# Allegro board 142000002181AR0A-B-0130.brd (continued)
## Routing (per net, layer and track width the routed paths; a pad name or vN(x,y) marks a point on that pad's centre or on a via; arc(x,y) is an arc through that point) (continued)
GND_1: length 19.4
  BOTTOM w0.381: H1.4 9.2,50.8 C6.1 7.87,49.78 5.29,52.37 H1.5 ; H1.3 11.37,55 C1.1 10.25,56.86 H1.2
GND_2: length 22.3
  BOTTOM w0.381: H5.4 9.68,26.14 C12.1 10.07,29.86 H5.2 6.86,32.82 C9.1 3.14,32.66 H5.8
GND_3: length 21.3
  BOTTOM w0.381: H2.4 124.57,53.14 C3.1 124.8,56.86 H2.2 ; H2.8 115.48,56.86 C2.1 115.72,53.14 H2.6
GND_4: length 21.8
  BOTTOM w0.381: H7.4 327.44,26.14 C13.1 327.83,29.86 H7.2 324.86,32.83 C11.1 321.14,32.65 H7.8
GND_5: length 21.8
  BOTTOM w0.381: H6.2 121.86,32.63 C10.1 118.14,32.85 H6.8 ; H6.6 118.14,23.28 C15.1 121.86,23.51 H6.4
GND_6: length 19.4
  BOTTOM w0.381: H3.5 258.13,50.24 C7.1 260.35,50.65 H3.4 260.2,53.14 C4.1 260.44,56.86 H3.2
GND_7: length 27.2
  BOTTOM w0.381: H9.7 252.58,5.79 C18.1 247.2,6.86 H9.8 ; H9.2 258.29,6.86 260.35,8.92 C17.1 259.28,9.91 258.83,9.91 256.55,7.63 H9.1
GND_8: length 21.5
  BOTTOM w0.381: H8.7 381.88,20 C16.1 382.07,20.63 383.3,21.86 H8.8 383.54,24.46 C14.1 384.16,26.47 H8.1
GND_9: length 19.3
  BOTTOM w0.381: H4.6 383.69,53.14 C5.1 383.45,56.86 H4.8 ; H4.5 388,49.08 C8.1 388.37,48.77 389.86,50.26 H4.4
MB_PDU_SCL_R: length 10.7
  BOTTOM w0.127: R29.2 270.96,13.01 v1(270.51,13.46) 269.59,12.54 269.59,7.12 270.11,6.61 270.99,6.61 CONN6.4
MB_PDU_SDA_R: length 6.9
  BOTTOM w0.127: R30.1 273.61,13.01 v1(274.07,13.46) 274.07,11.61 272.92,10.46 CONN6.5
PDU_12V: length 1887.2
  V3 w0.635: CONN2.P1-11 95.58,20.46 ; CONN2.P1-11 94.64,19.52 ; CONN2.P1-11 93.69,20.46 ; CONN2.P1-11 94.64,21.4 ; CONN3.P1-23 145.18,20.46 ; CONN3.P1-23 143.29,20.46 ; CONN3.P1-23 144.23,19.52 ; CONN3.P1-23 144.23,21.4 ; CONN2.P3-13 90.5,17.92 ; CONN2.P3-13 89.56,18.86 ; CONN2.P3-13 88.61,17.92 ; CONN2.P3-13 89.56,16.98 ; CONN5.P1 330.14,12.65 ; CONN5.P1 328.95,11.46 ; CONN5.P1 328.95,13.84 ; CONN4.P3-21 211.62,18.86 ; CONN4.P3-21 212.56,17.92 ; CONN4.P3-21 210.67,17.92 ; CONN4.P3-21 211.62,16.98 ; 84.48,16.98 CONN2.P3-22 ; CONN2.P3-22 85.42,17.92 ; CONN2.P3-22 83.53,17.92 ; CONN2.P3-22 84.48,18.86 ; CONN3.P1-22 147.72,20.46 ; CONN3.P1-22 146.77,19.52 ; CONN3.P1-22 146.77,21.4 ; CONN3.P1-22 145.83,20.46 ; CONN1.P3-21 25.66,17.92 ; CONN1.P3-21 24.71,16.98 ; CONN1.P3-21 23.77,17.92 ; CONN1.P3-21 24.71,18.86 ; CONN4.P3-22 210.02,17.92 ; CONN4.P3-22 209.08,16.98 ; CONN4.P3-22 209.08,18.86 ; CONN4.P3-22 208.13,17.92 ; CONN4.P1-21 212.56,20.46 ; CONN4.P1-21 211.62,21.4 ; CONN4.P1-21 211.62,19.52 ; CONN4.P1-21 210.67,20.46 ; CONN1.P1-13 28.2,20.46 ; CONN1.P1-13 27.25,21.4 ; CONN1.P1-13 26.31,20.46 ; CONN1.P1-13 27.25,19.52 ; CONN1.P3-13 28.2,17.92 ; CONN1.P3-13 27.25,16.98 ; CONN1.P3-13 26.31,17.92 ; CONN1.P3-13 27.25,18.86 ; 326.65,11.46 CONN5.P2 ; CONN5.P2 325.46,12.65 ; CONN5.P2 326.65,13.84 ; 18.69,20.46 CONN1.P1-23 ; CONN1.P1-23 19.63,21.4 ; CONN1.P1-23 20.58,20.46 ; CONN1.P1-23 19.63,19.52 ; 86.07,20.46 CONN2.P1-21 ; CONN2.P1-21 87.02,21.4 ; CONN2.P1-21 87.96,20.46 ; CONN2.P1-21 87.02,19.52 ; 28.85,17.92 CONN1.P3-12 ; CONN1.P3-12 30.74,17.92 ; CONN1.P3-12 29.79,18.86 ; CONN1.P3-12 29.79,16.98 ; CONN3.P1-13 152.8,20.46 ; CONN3.P1-13 151.85,21.4 ; CONN3.P1-13 151.85,19.52 ; CONN3.P1-13 150.91,20.46 ; CONN1.P3-22 22.17,18.86 ; CONN1.P3-22 21.23,17.92 ; CONN1.P3-22 23.12,17.92 ; CONN1.P3-22 22.17,16.98 ; 19.63,16.98 CONN1.P3-23 ; CONN1.P3-23 20.58,17.92 ; CONN1.P3-23 19.63,18.86 ; CONN1.P3-23 18.69,17.92 ; 215.75,20.46 CONN4.P1-12 ; CONN4.P1-12 216.7,19.52 ; CONN4.P1-12 216.7,21.4 ; CONN4.P1-12 217.64,20.46 ; CONN2.P1-23 82.88,20.46 ; CONN2.P1-23 81.94,19.52 ; CONN2.P1-23 80.99,20.46 ; CONN2.P1-23 81.94,21.4 ; 206.54,16.98 CONN4.P3-23 ; CONN4.P3-23 206.54,18.86 ; CONN4.P3-23 205.59,17.92 ; CONN4.P3-23 207.48,17.92 ; 213.21,20.46 CONN4.P1-13 ; CONN4.P1-13 215.1,20.46 ; CONN4.P1-13 214.16,19.52 ; CONN4.P1-13 214.16,21.4 ; 148.37,20.46 CONN3.P1-21 ; CONN3.P1-21 149.31,19.52 ; CONN3.P1-21 149.31,21.4 ; CONN3.P1-21 150.26,20.46 ; 146.77,16.98 CONN3.P3-22 ; CONN3.P3-22 146.77,18.86 ; CONN3.P3-22 145.83,17.92 ; CONN3.P3-22 147.72,17.92 ; 155.99,20.46 CONN3.P1-11 ; CONN3.P1-11 156.93,19.52 ; CONN3.P1-11 157.88,20.46 ; CONN3.P1-11 156.93,21.4 ; 205.59,20.46 CONN4.P1-23 ; CONN4.P1-23 206.54,19.52 ; CONN4.P1-23 206.54,21.4 ; CONN4.P1-23 207.48,20.46 ; CONN2.P3-23 81.94,18.86 ; CONN2.P3-23 82.88,17.92 ; CONN2.P3-23 81.94,16.98 ; CONN2.P3-23 80.99,17.92 ; CONN2.P3-21 87.02,18.86 ; CONN2.P3-21 87.02,16.98 ; CONN2.P3-21 87.96,17.92 ; CONN2.P3-21 86.07,17.92 ; CONN4.P1-11 219.24,21.4 ; CONN4.P1-11 218.29,20.46 ; CONN4.P1-11 220.18,20.46 ; CONN4.P1-11 219.24,19.52 ; 219.24,16.98 CONN4.P3-11 ; CONN4.P3-11 220.18,17.92 ; CONN4.P3-11 219.24,18.86 ; CONN4.P3-11 218.29,17.92 ; CONN2.P1-22 85.42,20.46 ; CONN2.P1-22 84.48,21.4 ; CONN2.P1-22 83.53,20.46 ; CONN2.P1-22 84.48,19.52 ; CONN3.P1-12 154.39,21.4 ; CONN3.P1-12 154.39,19.52 ; CONN3.P1-12 153.45,20.46 ; CONN3.P1-12 155.34,20.46 ; 32.33,19.52 CONN1.P1-11 ; CONN1.P1-11 33.28,20.46 ; CONN1.P1-11 32.33,21.4 ; CONN1.P1-11 31.39,20.46 ; 94.64,16.98 CONN2.P3-11 ; CONN2.P3-11 94.64,18.86 ; CONN2.P3-11 93.69,17.92 ; CONN2.P3-11 95.58,17.92 ; 24.71,19.52 CONN1.P1-21 ; CONN1.P1-21 23.77,20.46 ; CONN1.P1-21 24.71,21.4 ; CONN1.P1-21 25.66,20.46 ; CONN3.P3-11 157.88,17.92 ; CONN3.P3-11 156.93,18.86 ; CONN3.P3-11 156.93,16.98 ; CONN3.P3-11 155.99,17.92 ; 151.85,16.98 CONN3.P3-13 ; CONN3.P3-13 150.91,17.92 ; CONN3.P3-13 151.85,18.86 ; CONN3.P3-13 152.8,17.92 ; 148.37,17.92 CONN3.P3-21 ; CONN3.P3-21 150.26,17.92 ; CONN3.P3-21 149.31,16.98 ; CONN3.P3-21 149.31,18.86 ; 153.45,17.92 CONN3.P3-12 ; CONN3.P3-12 155.34,17.92 ; CONN3.P3-12 154.39,16.98 ; CONN3.P3-12 154.39,18.86 ; 31.39,17.92 CONN1.P3-11 ; CONN1.P3-11 33.28,17.92 ; CONN1.P3-11 32.33,16.98 ; CONN1.P3-11 32.33,18.86 ; CONN1.P1-12 29.79,21.4 ; CONN1.P1-12 30.74,20.46 ; CONN1.P1-12 28.85,20.46 ; CONN1.P1-12 29.79,19.52 ; CONN4.P3-13 214.16,18.86 ; CONN4.P3-13 213.21,17.92 ; CONN4.P3-13 214.16,16.98 ; CONN4.P3-13 215.1,17.92 ; 21.23,20.46 CONN1.P1-22 ; CONN1.P1-22 22.17,21.4 ; CONN1.P1-22 23.12,20.46 ; CONN1.P1-22 22.17,19.52 ; 215.75,17.92 CONN4.P3-12 ; CONN4.P3-12 216.7,16.98 ; CONN4.P3-12 217.64,17.92 ; CONN4.P3-12 216.7,18.86 ; CONN2.P1-12 92.1,21.4 ; CONN2.P1-12 91.15,20.46 ; CONN2.P1-12 93.04,20.46 ; CONN2.P1-12 92.1,19.52 ; 143.29,17.92 CONN3.P3-23 ; CONN3.P3-23 145.18,17.92 ; CONN3.P3-23 144.23,16.98 ; CONN3.P3-23 144.23,18.86 ; 91.15,17.92 CONN2.P3-12 ; CONN2.P3-12 92.1,18.86 ; CONN2.P3-12 92.1,16.98 ; CONN2.P3-12 93.04,17.92 ; CONN2.P1-13 89.56,21.4 ; CONN2.P1-13 88.61,20.46 ; CONN2.P1-13 89.56,19.52 ; CONN2.P1-13 90.5,20.46 ; CONN4.P1-22 209.08,21.4 ; CONN4.P1-22 210.02,20.46 ; CONN4.P1-22 208.13,20.46 ; CONN4.P1-22 209.08,19.52
  V5 w0.635: 92.1,16.98 CONN2.P3-12 ; CONN2.P3-12 93.04,17.92 ; CONN2.P3-12 92.1,18.86 ; CONN2.P3-12 91.15,17.92 ; CONN1.P3-11 32.33,18.86 ; CONN1.P3-11 33.28,17.92 ; CONN1.P3-11 31.39,17.92 ; CONN1.P3-11 32.33,16.98 ; 81.94,16.98 CONN2.P3-23 ; CONN2.P3-23 82.88,17.92 ; CONN2.P3-23 80.99,17.92 ; CONN2.P3-23 81.94,18.86 ; CONN3.P3-12 154.39,18.86 ; CONN3.P3-12 153.45,17.92 ; CONN3.P3-12 154.39,16.98 ; CONN3.P3-12 155.34,17.92 ; CONN3.P3-23 145.18,17.92 ; CONN3.P3-23 143.29,17.92 ; CONN3.P3-23 144.23,16.98 ; CONN3.P3-23 144.23,18.86 ; CONN3.P3-22 146.77,18.86 ; CONN3.P3-22 147.72,17.92 ; CONN3.P3-22 146.77,16.98 ; CONN3.P3-22 145.83,17.92 ; CONN2.P1-11 94.64,21.4 ; CONN2.P1-11 93.69,20.46 ; CONN2.P1-11 94.64,19.52 ; CONN2.P1-11 95.58,20.46 ; 156.93,19.52 CONN3.P1-11 ; CONN3.P1-11 155.99,20.46 ; CONN3.P1-11 157.88,20.46 ; CONN3.P1-11 156.93,21.4 ; 153.45,20.46 CONN3.P1-12 ; CONN3.P1-12 154.39,19.52 ; CONN3.P1-12 154.39,21.4 ; CONN3.P1-12 155.34,20.46 ; 22.17,16.98 CONN1.P3-22 ; CONN1.P3-22 22.17,18.86 ; CONN1.P3-22 23.12,17.92 ; CONN1.P3-22 21.23,17.92 ; CONN2.P3-13 90.5,17.92 ; CONN2.P3-13 88.61,17.92 ; CONN2.P3-13 89.56,18.86 ; CONN2.P3-13 89.56,16.98 ; CONN3.P1-23 145.18,20.46 ; CONN3.P1-23 143.29,20.46 ; CONN3.P1-23 144.23,21.4 ; CONN3.P1-23 144.23,19.52 ; 24.71,16.98 CONN1.P3-21 ; CONN1.P3-21 23.77,17.92 ; CONN1.P3-21 24.71,18.86 ; CONN1.P3-21 25.66,17.92 ; 27.25,16.98 CONN1.P3-13 ; CONN1.P3-13 28.2,17.92 ; CONN1.P3-13 27.25,18.86 ; CONN1.P3-13 26.31,17.92 ; CONN4.P1-11 219.24,21.4 ; CONN4.P1-11 219.24,19.52 ; CONN4.P1-11 218.29,20.46 ; CONN4.P1-11 220.18,20.46 ; CONN3.P3-21 149.31,18.86 ; CONN3.P3-21 150.26,17.92 ; CONN3.P3-21 148.37,17.92 ; CONN3.P3-21 149.31,16.98 ; CONN3.P3-13 152.8,17.92 ; CONN3.P3-13 151.85,16.98 ; CONN3.P3-13 150.91,17.92 ; CONN3.P3-13 151.85,18.86 ; CONN1.P1-22 22.17,21.4 ; CONN1.P1-22 21.23,20.46 ; CONN1.P1-22 23.12,20.46 ; CONN1.P1-22 22.17,19.52 ; CONN3.P1-13 152.8,20.46 ; CONN3.P1-13 151.85,19.52 ; CONN3.P1-13 151.85,21.4 ; CONN3.P1-13 150.91,20.46 ; CONN2.P1-12 93.04,20.46 ; CONN2.P1-12 92.1,19.52 ; CONN2.P1-12 92.1,21.4 ; CONN2.P1-12 91.15,20.46 ; 211.62,19.52 CONN4.P1-21 ; CONN4.P1-21 210.67,20.46 ; CONN4.P1-21 211.62,21.4 ; CONN4.P1-21 212.56,20.46 ; 84.48,19.52 CONN2.P1-22 ; CONN2.P1-22 85.42,20.46 ; CONN2.P1-22 83.53,20.46 ; CONN2.P1-22 84.48,21.4 ; 328.95,11.46 CONN5.P1 ; CONN5.P1 328.95,13.84 ; CONN5.P1 330.14,12.65 ; CONN4.P3-23 206.54,18.86 ; CONN4.P3-23 206.54,16.98 ; CONN4.P3-23 205.59,17.92 ; CONN4.P3-23 207.48,17.92 ; 29.79,16.98 CONN1.P3-12 ; CONN1.P3-12 30.74,17.92 ; CONN1.P3-12 29.79,18.86 ; CONN1.P3-12 28.85,17.92 ; CONN1.P1-21 24.71,21.4 ; CONN1.P1-21 24.71,19.52 ; CONN1.P1-21 25.66,20.46 ; CONN1.P1-21 23.77,20.46 ; 28.85,20.46 CONN1.P1-12 ; CONN1.P1-12 29.79,19.52 ; CONN1.P1-12 29.79,21.4 ; CONN1.P1-12 30.74,20.46 ; 86.07,20.46 CONN2.P1-21 ; CONN2.P1-21 87.02,21.4 ; CONN2.P1-21 87.96,20.46 ; CONN2.P1-21 87.02,19.52 ; CONN4.P3-12 217.64,17.92 ; CONN4.P3-12 216.7,16.98 ; CONN4.P3-12 215.75,17.92 ; CONN4.P3-12 216.7,18.86 ; 26.31,20.46 CONN1.P1-13 ; CONN1.P1-13 28.2,20.46 ; CONN1.P1-13 27.25,19.52 ; CONN1.P1-13 27.25,21.4 ; 205.59,20.46 CONN4.P1-23 ; CONN4.P1-23 206.54,21.4 ; CONN4.P1-23 206.54,19.52 ; CONN4.P1-23 207.48,20.46 ; CONN4.P3-11 220.18,17.92 ; CONN4.P3-11 218.29,17.92 ; CONN4.P3-11 219.24,16.98 ; CONN4.P3-11 219.24,18.86 ; 89.56,19.52 CONN2.P1-13 ; CONN2.P1-13 90.5,20.46 ; CONN2.P1-13 89.56,21.4 ; CONN2.P1-13 88.61,20.46 ; 83.53,17.92 CONN2.P3-22 ; CONN2.P3-22 84.48,16.98 ; CONN2.P3-22 84.48,18.86 ; CONN2.P3-22 85.42,17.92 ; 86.07,17.92 CONN2.P3-21 ; CONN2.P3-21 87.02,16.98 ; CONN2.P3-21 87.02,18.86 ; CONN2.P3-21 87.96,17.92 ; 18.69,20.46 CONN1.P1-23 ; CONN1.P1-23 19.63,21.4 ; CONN1.P1-23 19.63,19.52 ; CONN1.P1-23 20.58,20.46 ; CONN4.P3-13 215.1,17.92 ; CONN4.P3-13 214.16,18.86 ; CONN4.P3-13 214.16,16.98 ; CONN4.P3-13 213.21,17.92 ; CONN3.P1-21 149.31,21.4 ; CONN3.P1-21 150.26,20.46 ; CONN3.P1-21 149.31,19.52 ; CONN3.P1-21 148.37,20.46 ; CONN4.P3-21 211.62,18.86 ; CONN4.P3-21 211.62,16.98 ; CONN4.P3-21 212.56,17.92 ; CONN4.P3-21 210.67,17.92 ; CONN1.P3-23 20.58,17.92 ; CONN1.P3-23 19.63,16.98 ; CONN1.P3-23 18.69,17.92 ; CONN1.P3-23 19.63,18.86 ; 155.99,17.92 CONN3.P3-11 ; CONN3.P3-11 157.88,17.92 ; CONN3.P3-11 156.93,16.98 ; CONN3.P3-11 156.93,18.86 ; 326.65,11.46 CONN5.P2 ; CONN5.P2 326.65,13.84 ; CONN5.P2 325.46,12.65 ; CONN2.P1-23 82.88,20.46 ; CONN2.P1-23 81.94,21.4 ; CONN2.P1-23 80.99,20.46 ; CONN2.P1-23 81.94,19.52 ; 208.13,20.46 CONN4.P1-22 ; CONN4.P1-22 209.08,19.52 ; CONN4.P1-22 210.02,20.46 ; CONN4.P1-22 209.08,21.4 ; 93.69,17.92 CONN2.P3-11 ; CONN2.P3-11 94.64,16.98 ; CONN2.P3-11 95.58,17.92 ; CONN2.P3-11 94.64,18.86 ; 145.83,20.46 CONN3.P1-22 ; CONN3.P1-22 147.72,20.46 ; CONN3.P1-22 146.77,19.52 ; CONN3.P1-22 146.77,21.4 ; CONN4.P3-22 210.02,17.92 ; CONN4.P3-22 209.08,16.98 ; CONN4.P3-22 209.08,18.86 ; CONN4.P3-22 208.13,17.92 ; 31.39,20.46 CONN1.P1-11 ; CONN1.P1-11 32.33,21.4 ; CONN1.P1-11 33.28,20.46 ; CONN1.P1-11 32.33,19.52 ; 214.16,19.52 CONN4.P1-13 ; CONN4.P1-13 214.16,21.4 ; CONN4.P1-13 215.1,20.46 ; CONN4.P1-13 213.21,20.46 ; CONN4.P1-12 216.7,21.4 ; CONN4.P1-12 215.75,20.46 ; CONN4.P1-12 216.7,19.52 ; CONN4.P1-12 217.64,20.46
  V7 w0.635: CONN4.P1-12 217.64,20.46 ; CONN4.P1-12 216.7,19.52 ; CONN4.P1-12 215.75,20.46 ; CONN4.P1-12 216.7,21.4 ; 92.1,19.52 CONN2.P1-12 ; CONN2.P1-12 93.04,20.46 ; CONN2.P1-12 91.15,20.46 ; CONN2.P1-12 92.1,21.4 ; CONN3.P3-11 156.93,18.86 ; CONN3.P3-11 155.99,17.92 ; CONN3.P3-11 157.88,17.92 ; CONN3.P3-11 156.93,16.98 ; 219.24,16.98 CONN4.P3-11 ; CONN4.P3-11 220.18,17.92 ; CONN4.P3-11 218.29,17.92 ; CONN4.P3-11 219.24,18.86 ; CONN2.P1-22 85.42,20.46 ; CONN2.P1-22 84.48,19.52 ; CONN2.P1-22 83.53,20.46 ; CONN2.P1-22 84.48,21.4 ; 31.39,20.46 CONN1.P1-11 ; CONN1.P1-11 32.33,21.4 ; CONN1.P1-11 33.28,20.46 ; CONN1.P1-11 32.33,19.52 ; 22.17,16.98 CONN1.P3-22 ; CONN1.P3-22 22.17,18.86 ; CONN1.P3-22 23.12,17.92 ; CONN1.P3-22 21.23,17.92 ; 23.77,20.46 CONN1.P1-21 ; CONN1.P1-21 24.71,21.4 ; CONN1.P1-21 25.66,20.46 ; CONN1.P1-21 24.71,19.52 ; CONN4.P1-21 212.56,20.46 ; CONN4.P1-21 211.62,21.4 ; CONN4.P1-21 211.62,19.52 ; CONN4.P1-21 210.67,20.46 ; CONN1.P1-12 30.74,20.46 ; CONN1.P1-12 28.85,20.46 ; CONN1.P1-12 29.79,21.4 ; CONN1.P1-12 29.79,19.52 ; 89.56,16.98 CONN2.P3-13 ; CONN2.P3-13 90.5,17.92 ; CONN2.P3-13 88.61,17.92 ; CONN2.P3-13 89.56,18.86 ; 145.83,20.46 CONN3.P1-22 ; CONN3.P1-22 146.77,19.52 ; CONN3.P1-22 146.77,21.4 ; CONN3.P1-22 147.72,20.46 ; 214.16,19.52 CONN4.P1-13 ; CONN4.P1-13 215.1,20.46 ; CONN4.P1-13 214.16,21.4 ; CONN4.P1-13 213.21,20.46 ; CONN4.P3-12 217.64,17.92 ; CONN4.P3-12 216.7,18.86 ; CONN4.P3-12 216.7,16.98 ; CONN4.P3-12 215.75,17.92 ; CONN1.P3-13 27.25,18.86 ; CONN1.P3-13 26.31,17.92 ; CONN1.P3-13 27.25,16.98 ; CONN1.P3-13 28.2,17.92 ; CONN3.P3-23 145.18,17.92 ; CONN3.P3-23 144.23,16.98 ; CONN3.P3-23 143.29,17.92 ; CONN3.P3-23 144.23,18.86 ; CONN4.P1-22 209.08,21.4 ; CONN4.P1-22 208.13,20.46 ; CONN4.P1-22 210.02,20.46 ; CONN4.P1-22 209.08,19.52 ; CONN1.P1-22 22.17,21.4 ; CONN1.P1-22 22.17,19.52 ; CONN1.P1-22 21.23,20.46 ; CONN1.P1-22 23.12,20.46 ; CONN1.P1-13 27.25,21.4 ; CONN1.P1-13 26.31,20.46 ; CONN1.P1-13 27.25,19.52 ; CONN1.P1-13 28.2,20.46 ; 154.39,19.52 CONN3.P1-12 ; CONN3.P1-12 154.39,21.4 ; CONN3.P1-12 155.34,20.46 ; CONN3.P1-12 153.45,20.46 ; CONN1.P3-21 24.71,18.86 ; CONN1.P3-21 25.66,17.92 ; CONN1.P3-21 24.71,16.98 ; CONN1.P3-21 23.77,17.92 ; 94.64,19.52 CONN2.P1-11 ; CONN2.P1-11 95.58,20.46 ; CONN2.P1-11 94.64,21.4 ; CONN2.P1-11 93.69,20.46 ; CONN3.P3-12 155.34,17.92 ; CONN3.P3-12 154.39,16.98 ; CONN3.P3-12 153.45,17.92 ; CONN3.P3-12 154.39,18.86 ; 81.94,16.98 CONN2.P3-23 ; CONN2.P3-23 82.88,17.92 ; CONN2.P3-23 80.99,17.92 ; CONN2.P3-23 81.94,18.86 ; 89.56,19.52 CONN2.P1-13 ; CONN2.P1-13 90.5,20.46 ; CONN2.P1-13 89.56,21.4 ; CONN2.P1-13 88.61,20.46 ; 31.39,17.92 CONN1.P3-11 ; CONN1.P3-11 32.33,18.86 ; CONN1.P3-11 32.33,16.98 ; CONN1.P3-11 33.28,17.92 ; 92.1,16.98 CONN2.P3-12 ; CONN2.P3-12 91.15,17.92 ; CONN2.P3-12 92.1,18.86 ; CONN2.P3-12 93.04,17.92 ; CONN4.P3-23 207.48,17.92 ; CONN4.P3-23 206.54,16.98 ; CONN4.P3-23 205.59,17.92 ; CONN4.P3-23 206.54,18.86 ; 143.29,20.46 CONN3.P1-23 ; CONN3.P1-23 144.23,19.52 ; CONN3.P1-23 145.18,20.46 ; CONN3.P1-23 144.23,21.4 ; CONN1.P3-23 19.63,18.86 ; CONN1.P3-23 18.69,17.92 ; CONN1.P3-23 19.63,16.98 ; CONN1.P3-23 20.58,17.92 ; CONN2.P3-22 85.42,17.92 ; CONN2.P3-22 83.53,17.92 ; CONN2.P3-22 84.48,18.86 ; CONN2.P3-22 84.48,16.98 ; CONN3.P1-11 156.93,21.4 ; CONN3.P1-11 156.93,19.52 ; CONN3.P1-11 157.88,20.46 ; CONN3.P1-11 155.99,20.46 ; 86.07,17.92 CONN2.P3-21 ; CONN2.P3-21 87.02,18.86 ; CONN2.P3-21 87.96,17.92 ; CONN2.P3-21 87.02,16.98 ; 213.21,17.92 CONN4.P3-13 ; CONN4.P3-13 215.1,17.92 ; CONN4.P3-13 214.16,18.86 ; CONN4.P3-13 214.16,16.98 ; 150.91,20.46 CONN3.P1-13 ; CONN3.P1-13 151.85,21.4 ; CONN3.P1-13 152.8,20.46 ; CONN3.P1-13 151.85,19.52 ; 205.59,20.46 CONN4.P1-23 ; CONN4.P1-23 206.54,19.52 ; CONN4.P1-23 207.48,20.46 ; CONN4.P1-23 206.54,21.4 ; 211.62,16.98 CONN4.P3-21 ; CONN4.P3-21 212.56,17.92 ; CONN4.P3-21 211.62,18.86 ; CONN4.P3-21 210.67,17.92 ; CONN2.P1-23 82.88,20.46 ; CONN2.P1-23 80.99,20.46 ; CONN2.P1-23 81.94,19.52 ; CONN2.P1-23 81.94,21.4 ; CONN1.P3-12 29.79,18.86 ; CONN1.P3-12 28.85,17.92 ; CONN1.P3-12 30.74,17.92 ; CONN1.P3-12 29.79,16.98 ; CONN3.P3-13 152.8,17.92 ; CONN3.P3-13 151.85,16.98 ; CONN3.P3-13 150.91,17.92 ; CONN3.P3-13 151.85,18.86 ; 18.69,20.46 CONN1.P1-23 ; CONN1.P1-23 19.63,19.52 ; CONN1.P1-23 19.63,21.4 ; CONN1.P1-23 20.58,20.46 ; CONN5.P1 330.14,12.65 ; CONN5.P1 328.95,13.84 ; CONN5.P1 328.95,11.46 ; 145.83,17.92 CONN3.P3-22 ; CONN3.P3-22 146.77,18.86 ; CONN3.P3-22 146.77,16.98 ; CONN3.P3-22 147.72,17.92 ; CONN4.P1-11 219.24,21.4 ; CONN4.P1-11 220.18,20.46 ; CONN4.P1-11 219.24,19.52 ; CONN4.P1-11 218.29,20.46 ; 208.13,17.92 CONN4.P3-22 ; CONN4.P3-22 209.08,18.86 ; CONN4.P3-22 209.08,16.98 ; CONN4.P3-22 210.02,17.92 ; CONN2.P1-21 87.02,21.4 ; CONN2.P1-21 86.07,20.46 ; CONN2.P1-21 87.96,20.46 ; CONN2.P1-21 87.02,19.52 ; 149.31,19.52 CONN3.P1-21 ; CONN3.P1-21 149.31,21.4 ; CONN3.P1-21 148.37,20.46 ; CONN3.P1-21 150.26,20.46 ; 325.46,12.65 CONN5.P2 ; CONN5.P2 326.65,13.84 ; CONN5.P2 326.65,11.46 ; 148.37,17.92 CONN3.P3-21 ; CONN3.P3-21 149.31,16.98 ; CONN3.P3-21 150.26,17.92 ; CONN3.P3-21 149.31,18.86 ; CONN2.P3-11 95.58,17.92 ; CONN2.P3-11 93.69,17.92 ; CONN2.P3-11 94.64,16.98 ; CONN2.P3-11 94.64,18.86
  V9 w0.635: CONN2.P1-12 92.1,21.4 ; CONN2.P1-12 93.04,20.46 ; CONN2.P1-12 92.1,19.52 ; CONN2.P1-12 91.15,20.46 ; CONN1.P3-11 33.28,17.92 ; CONN1.P3-11 32.33,16.98 ; CONN1.P3-11 31.39,17.92 ; CONN1.P3-11 32.33,18.86 ; CONN4.P3-12 217.64,17.92 ; CONN4.P3-12 216.7,18.86 ; CONN4.P3-12 216.7,16.98 ; CONN4.P3-12 215.75,17.92 ; CONN2.P3-11 94.64,18.86 ; CONN2.P3-11 94.64,16.98 ; CONN2.P3-11 95.58,17.92 ; CONN2.P3-11 93.69,17.92 ; 153.45,17.92 CONN3.P3-12 ; CONN3.P3-12 155.34,17.92 ; CONN3.P3-12 154.39,18.86 ; CONN3.P3-12 154.39,16.98 ; 156.93,19.52 CONN3.P1-11 ; CONN3.P1-11 157.88,20.46 ; CONN3.P1-11 155.99,20.46 ; CONN3.P1-11 156.93,21.4 ; 148.37,20.46 CONN3.P1-21 ; CONN3.P1-21 149.31,21.4 ; CONN3.P1-21 149.31,19.52 ; CONN3.P1-21 150.26,20.46 ; CONN4.P3-21 211.62,18.86 ; CONN4.P3-21 210.67,17.92 ; CONN4.P3-21 211.62,16.98 ; CONN4.P3-21 212.56,17.92 ; CONN2.P1-21 87.02,21.4 ; CONN2.P1-21 86.07,20.46 ; CONN2.P1-21 87.02,19.52 ; CONN2.P1-21 87.96,20.46 ; 84.48,19.52 CONN2.P1-22 ; CONN2.P1-22 83.53,20.46 ; CONN2.P1-22 84.48,21.4 ; CONN2.P1-22 85.42,20.46 ; 143.29,17.92 CONN3.P3-23 ; CONN3.P3-23 144.23,18.86 ; CONN3.P3-23 145.18,17.92 ; CONN3.P3-23 144.23,16.98 ; CONN2.P1-11 95.58,20.46 ; CONN2.P1-11 94.64,19.52 ; CONN2.P1-11 94.64,21.4 ; CONN2.P1-11 93.69,20.46 ; 149.31,16.98 CONN3.P3-21 ; CONN3.P3-21 148.37,17.92 ; CONN3.P3-21 150.26,17.92 ; CONN3.P3-21 149.31,18.86 ; 89.56,19.52 CONN2.P1-13 ; CONN2.P1-13 90.5,20.46 ; CONN2.P1-13 88.61,20.46 ; CONN2.P1-13 89.56,21.4 ; 19.63,19.52 CONN1.P1-23 ; CONN1.P1-23 19.63,21.4 ; CONN1.P1-23 18.69,20.46 ; CONN1.P1-23 20.58,20.46 ; CONN1.P1-11 33.28,20.46 ; CONN1.P1-11 32.33,19.52 ; CONN1.P1-11 31.39,20.46 ; CONN1.P1-11 32.33,21.4 ; CONN1.P1-12 30.74,20.46 ; CONN1.P1-12 28.85,20.46 ; CONN1.P1-12 29.79,19.52 ; CONN1.P1-12 29.79,21.4 ; 84.48,16.98 CONN2.P3-22 ; CONN2.P3-22 83.53,17.92 ; CONN2.P3-22 85.42,17.92 ; CONN2.P3-22 84.48,18.86 ; 208.13,17.92 CONN4.P3-22 ; CONN4.P3-22 209.08,18.86 ; CONN4.P3-22 210.02,17.92 ; CONN4.P3-22 209.08,16.98 ; CONN3.P1-23 145.18,20.46 ; CONN3.P1-23 144.23,21.4 ; CONN3.P1-23 144.23,19.52 ; CONN3.P1-23 143.29,20.46 ; CONN4.P3-23 207.48,17.92 ; CONN4.P3-23 205.59,17.92 ; CONN4.P3-23 206.54,16.98 ; CONN4.P3-23 206.54,18.86 ; CONN1.P3-12 30.74,17.92 ; CONN1.P3-12 28.85,17.92 ; CONN1.P3-12 29.79,18.86 ; CONN1.P3-12 29.79,16.98 ; CONN5.P1 330.14,12.65 ; CONN5.P1 328.95,13.84 ; CONN5.P1 328.95,11.46 ; CONN4.P1-11 220.18,20.46 ; CONN4.P1-11 218.29,20.46 ; CONN4.P1-11 219.24,21.4 ; CONN4.P1-11 219.24,19.52 ; CONN2.P3-12 93.04,17.92 ; CONN2.P3-12 91.15,17.92 ; CONN2.P3-12 92.1,16.98 ; CONN2.P3-12 92.1,18.86 ; CONN4.P1-21 212.56,20.46 ; CONN4.P1-21 211.62,19.52 ; CONN4.P1-21 210.67,20.46 ; CONN4.P1-21 211.62,21.4 ; CONN4.P1-23 206.54,21.4 ; CONN4.P1-23 207.48,20.46 ; CONN4.P1-23 206.54,19.52 ; CONN4.P1-23 205.59,20.46 ; 156.93,16.98 CONN3.P3-11 ; CONN3.P3-11 157.88,17.92 ; CONN3.P3-11 155.99,17.92 ; CONN3.P3-11 156.93,18.86 ; CONN4.P3-11 220.18,17.92 ; CONN4.P3-11 219.24,16.98 ; CONN4.P3-11 218.29,17.92 ; CONN4.P3-11 219.24,18.86 ; 22.17,16.98 CONN1.P3-22 ; CONN1.P3-22 21.23,17.92 ; CONN1.P3-22 22.17,18.86 ; CONN1.P3-22 23.12,17.92 ; CONN2.P1-23 82.88,20.46 ; CONN2.P1-23 81.94,19.52 ; CONN2.P1-23 81.94,21.4 ; CONN2.P1-23 80.99,20.46 ; 27.25,19.52 CONN1.P1-13 ; CONN1.P1-13 28.2,20.46 ; CONN1.P1-13 26.31,20.46 ; CONN1.P1-13 27.25,21.4 ; CONN2.P3-21 87.96,17.92 ; CONN2.P3-21 87.02,16.98 ; CONN2.P3-21 86.07,17.92 ; CONN2.P3-21 87.02,18.86 ; CONN1.P3-21 25.66,17.92 ; CONN1.P3-21 24.71,18.86 ; CONN1.P3-21 23.77,17.92 ; CONN1.P3-21 24.71,16.98 ; CONN3.P1-22 146.77,21.4 ; CONN3.P1-22 147.72,20.46 ; CONN3.P1-22 145.83,20.46 ; CONN3.P1-22 146.77,19.52 ; CONN4.P1-22 210.02,20.46 ; CONN4.P1-22 208.13,20.46 ; CONN4.P1-22 209.08,21.4 ; CONN4.P1-22 209.08,19.52 ; 213.21,17.92 CONN4.P3-13 ; CONN4.P3-13 215.1,17.92 ; CONN4.P3-13 214.16,18.86 ; CONN4.P3-13 214.16,16.98 ; 26.31,17.92 CONN1.P3-13 ; CONN1.P3-13 28.2,17.92 ; CONN1.P3-13 27.25,18.86 ; CONN1.P3-13 27.25,16.98 ; CONN3.P1-13 151.85,21.4 ; CONN3.P1-13 152.8,20.46 ; CONN3.P1-13 150.91,20.46 ; CONN3.P1-13 151.85,19.52 ; CONN1.P1-21 25.66,20.46 ; CONN1.P1-21 23.77,20.46 ; CONN1.P1-21 24.71,19.52 ; CONN1.P1-21 24.71,21.4 ; CONN4.P1-13 215.1,20.46 ; CONN4.P1-13 213.21,20.46 ; CONN4.P1-13 214.16,21.4 ; CONN4.P1-13 214.16,19.52 ; CONN4.P1-12 216.7,21.4 ; CONN4.P1-12 215.75,20.46 ; CONN4.P1-12 217.64,20.46 ; CONN4.P1-12 216.7,19.52 ; CONN3.P3-13 151.85,18.86 ; CONN3.P3-13 152.8,17.92 ; CONN3.P3-13 150.91,17.92 ; CONN3.P3-13 151.85,16.98 ; CONN1.P1-22 23.12,20.46 ; CONN1.P1-22 22.17,19.52 ; CONN1.P1-22 22.17,21.4 ; CONN1.P1-22 21.23,20.46 ; CONN3.P1-12 154.39,21.4 ; CONN3.P1-12 153.45,20.46 ; CONN3.P1-12 154.39,19.52 ; CONN3.P1-12 155.34,20.46 ; 88.61,17.92 CONN2.P3-13 ; CONN2.P3-13 89.56,16.98 ; CONN2.P3-13 89.56,18.86 ; CONN2.P3-13 90.5,17.92 ; 19.63,16.98 CONN1.P3-23 ; CONN1.P3-23 18.69,17.92 ; CONN1.P3-23 20.58,17.92 ; CONN1.P3-23 19.63,18.86 ; 80.99,17.92 CONN2.P3-23 ; CONN2.P3-23 81.94,16.98 ; CONN2.P3-23 82.88,17.92 ; CONN2.P3-23 81.94,18.86 ; CONN5.P2 326.65,13.84 ; CONN5.P2 325.46,12.65 ; CONN5.P2 326.65,11.46 ; 146.77,16.98 CONN3.P3-22 ; CONN3.P3-22 147.72,17.92 ; CONN3.P3-22 145.83,17.92 ; CONN3.P3-22 146.77,18.86
  V11 w0.635: 219.24,16.98 CONN4.P3-11 ; CONN4.P3-11 218.29,17.92 ; CONN4.P3-11 220.18,17.92 ; CONN4.P3-11 219.24,18.86 ; 24.71,16.98 CONN1.P3-21 ; CONN1.P3-21 24.71,18.86 ; CONN1.P3-21 23.77,17.92 ; CONN1.P3-21 25.66,17.92 ; CONN4.P1-11 220.18,20.46 ; CONN4.P1-11 219.24,19.52 ; CONN4.P1-11 218.29,20.46 ; CONN4.P1-11 219.24,21.4 ; 208.13,17.92 CONN4.P3-22 ; CONN4.P3-22 209.08,16.98 ; CONN4.P3-22 210.02,17.92 ; CONN4.P3-22 209.08,18.86 ; CONN3.P1-23 144.23,21.4 ; CONN3.P1-23 145.18,20.46 ; CONN3.P1-23 144.23,19.52 ; CONN3.P1-23 143.29,20.46 ; CONN2.P1-12 93.04,20.46 ; CONN2.P1-12 91.15,20.46 ; CONN2.P1-12 92.1,21.4 ; CONN2.P1-12 92.1,19.52 ; CONN5.P2 326.65,13.84 ; CONN5.P2 326.65,11.46 ; CONN5.P2 325.46,12.65 ; CONN4.P3-13 214.16,18.86 ; CONN4.P3-13 213.21,17.92 ; CONN4.P3-13 215.1,17.92 ; CONN4.P3-13 214.16,16.98 ; CONN1.P3-22 23.12,17.92 ; CONN1.P3-22 22.17,16.98 ; CONN1.P3-22 21.23,17.92 ; CONN1.P3-22 22.17,18.86 ; CONN3.P1-11 157.88,20.46 ; CONN3.P1-11 156.93,19.52 ; CONN3.P1-11 155.99,20.46 ; CONN3.P1-11 156.93,21.4 ; CONN2.P1-13 90.5,20.46 ; CONN2.P1-13 89.56,21.4 ; CONN2.P1-13 88.61,20.46 ; CONN2.P1-13 89.56,19.52 ; 148.37,20.46 CONN3.P1-21 ; CONN3.P1-21 149.31,21.4 ; CONN3.P1-21 149.31,19.52 ; CONN3.P1-21 150.26,20.46 ; 146.77,16.98 CONN3.P3-22 ; CONN3.P3-22 147.72,17.92 ; CONN3.P3-22 145.83,17.92 ; CONN3.P3-22 146.77,18.86 ; CONN2.P3-22 84.48,18.86 ; CONN2.P3-22 84.48,16.98 ; CONN2.P3-22 85.42,17.92 ; CONN2.P3-22 83.53,17.92 ; CONN3.P3-13 152.8,17.92 ; CONN3.P3-13 151.85,18.86 ; CONN3.P3-13 150.91,17.92 ; CONN3.P3-13 151.85,16.98 ; CONN1.P1-23 20.58,20.46 ; CONN1.P1-23 19.63,19.52 ; CONN1.P1-23 18.69,20.46 ; CONN1.P1-23 19.63,21.4 ; CONN3.P3-23 145.18,17.92 ; CONN3.P3-23 144.23,18.86 ; CONN3.P3-23 143.29,17.92 ; CONN3.P3-23 144.23,16.98 ; 81.94,16.98 CONN2.P3-23 ; CONN2.P3-23 81.94,18.86 ; CONN2.P3-23 82.88,17.92 ; CONN2.P3-23 80.99,17.92 ; 94.64,16.98 CONN2.P3-11 ; CONN2.P3-11 93.69,17.92 ; CONN2.P3-11 95.58,17.92 ; CONN2.P3-11 94.64,18.86 ; 81.94,19.52 CONN2.P1-23 ; CONN2.P1-23 82.88,20.46 ; CONN2.P1-23 80.99,20.46 ; CONN2.P1-23 81.94,21.4 ; CONN1.P3-13 27.25,18.86 ; CONN1.P3-13 26.31,17.92 ; CONN1.P3-13 28.2,17.92 ; CONN1.P3-13 27.25,16.98 ; CONN2.P1-22 84.48,21.4 ; CONN2.P1-22 83.53,20.46 ; CONN2.P1-22 85.42,20.46 ; CONN2.P1-22 84.48,19.52 ; CONN4.P3-21 212.56,17.92 ; CONN4.P3-21 210.67,17.92 ; CONN4.P3-21 211.62,18.86 ; CONN4.P3-21 211.62,16.98 ; 205.59,20.46 CONN4.P1-23 ; CONN4.P1-23 207.48,20.46 ; CONN4.P1-23 206.54,19.52 ; CONN4.P1-23 206.54,21.4 ; 23.77,20.46 CONN1.P1-21 ; CONN1.P1-21 24.71,19.52 ; CONN1.P1-21 25.66,20.46 ; CONN1.P1-21 24.71,21.4 ; 208.13,20.46 CONN4.P1-22 ; CONN4.P1-22 209.08,19.52 ; CONN4.P1-22 209.08,21.4 ; CONN4.P1-22 210.02,20.46 ; CONN3.P1-12 155.34,20.46 ; CONN3.P1-12 154.39,19.52 ; CONN3.P1-12 154.39,21.4 ; CONN3.P1-12 153.45,20.46 ; 19.63,16.98 CONN1.P3-23 ; CONN1.P3-23 18.69,17.92 ; CONN1.P3-23 19.63,18.86 ; CONN1.P3-23 20.58,17.92 ; CONN4.P1-12 217.64,20.46 ; CONN4.P1-12 215.75,20.46 ; CONN4.P1-12 216.7,21.4 ; CONN4.P1-12 216.7,19.52 ; CONN3.P1-22 147.72,20.46 ; CONN3.P1-22 146.77,21.4 ; CONN3.P1-22 145.83,20.46 ; CONN3.P1-22 146.77,19.52 ; 155.99,17.92 CONN3.P3-11 ; CONN3.P3-11 156.93,18.86 ; CONN3.P3-11 157.88,17.92 ; CONN3.P3-11 156.93,16.98 ; 32.33,19.52 CONN1.P1-11 ; CONN1.P1-11 33.28,20.46 ; CONN1.P1-11 32.33,21.4 ; CONN1.P1-11 31.39,20.46 ; CONN2.P3-13 89.56,18.86 ; CONN2.P3-13 89.56,16.98 ; CONN2.P3-13 90.5,17.92 ; CONN2.P3-13 88.61,17.92 ; 215.75,17.92 CONN4.P3-12 ; CONN4.P3-12 216.7,18.86 ; CONN4.P3-12 216.7,16.98 ; CONN4.P3-12 217.64,17.92 ; CONN1.P1-12 29.79,21.4 ; CONN1.P1-12 30.74,20.46 ; CONN1.P1-12 28.85,20.46 ; CONN1.P1-12 29.79,19.52 ; 213.21,20.46 CONN4.P1-13 ; CONN4.P1-13 215.1,20.46 ; CONN4.P1-13 214.16,19.52 ; CONN4.P1-13 214.16,21.4 ; CONN1.P1-22 23.12,20.46 ; CONN1.P1-22 22.17,21.4 ; CONN1.P1-22 21.23,20.46 ; CONN1.P1-22 22.17,19.52 ; CONN2.P1-21 87.96,20.46 ; CONN2.P1-21 86.07,20.46 ; CONN2.P1-21 87.02,19.52 ; CONN2.P1-21 87.02,21.4 ; CONN1.P3-11 32.33,18.86 ; CONN1.P3-11 32.33,16.98 ; CONN1.P3-11 31.39,17.92 ; CONN1.P3-11 33.28,17.92 ; CONN1.P1-13 28.2,20.46 ; CONN1.P1-13 27.25,21.4 ; CONN1.P1-13 26.31,20.46 ; CONN1.P1-13 27.25,19.52 ; CONN4.P1-21 212.56,20.46 ; CONN4.P1-21 211.62,19.52 ; CONN4.P1-21 211.62,21.4 ; CONN4.P1-21 210.67,20.46 ; 328.95,11.46 CONN5.P1 ; CONN5.P1 328.95,13.84 ; CONN5.P1 330.14,12.65 ; CONN3.P1-13 152.8,20.46 ; CONN3.P1-13 151.85,19.52 ; CONN3.P1-13 150.91,20.46 ; CONN3.P1-13 151.85,21.4 ; 206.54,16.98 CONN4.P3-23 ; CONN4.P3-23 205.59,17.92 ; CONN4.P3-23 207.48,17.92 ; CONN4.P3-23 206.54,18.86 ; 29.79,16.98 CONN1.P3-12 ; CONN1.P3-12 30.74,17.92 ; CONN1.P3-12 28.85,17.92 ; CONN1.P3-12 29.79,18.86 ; CONN3.P3-21 150.26,17.92 ; CONN3.P3-21 148.37,17.92 ; CONN3.P3-21 149.31,16.98 ; CONN3.P3-21 149.31,18.86 ; CONN3.P3-12 154.39,18.86 ; CONN3.P3-12 155.34,17.92 ; CONN3.P3-12 154.39,16.98 ; CONN3.P3-12 153.45,17.92 ; 86.07,17.92 CONN2.P3-21 ; CONN2.P3-21 87.02,16.98 ; CONN2.P3-21 87.96,17.92 ; CONN2.P3-21 87.02,18.86 ; CONN2.P1-11 95.58,20.46 ; CONN2.P1-11 94.64,21.4 ; CONN2.P1-11 93.69,20.46 ; CONN2.P1-11 94.64,19.52 ; CONN2.P3-12 92.1,18.86 ; CONN2.P3-12 91.15,17.92 ; CONN2.P3-12 92.1,16.98 ; CONN2.P3-12 93.04,17.92
  V12 w0.635: 215.75,20.46 CONN4.P1-12 ; CONN4.P1-12 217.64,20.46 ; CONN4.P1-12 216.7,19.52 ; CONN4.P1-12 216.7,21.4 ; CONN1.P3-11 33.28,17.92 ; CONN1.P3-11 32.33,18.86 ; CONN1.P3-11 32.33,16.98 ; CONN1.P3-11 31.39,17.92 ; CONN2.P1-21 87.02,21.4 ; CONN2.P1-21 86.07,20.46 ; CONN2.P1-21 87.96,20.46 ; CONN2.P1-21 87.02,19.52 ; CONN3.P1-13 151.85,21.4 ; CONN3.P1-13 151.85,19.52 ; CONN3.P1-13 150.91,20.46 ; CONN3.P1-13 152.8,20.46 ; 213.21,17.92 CONN4.P3-13 ; CONN4.P3-13 214.16,16.98 ; CONN4.P3-13 214.16,18.86 ; CONN4.P3-13 215.1,17.92 ; 81.94,19.52 CONN2.P1-23 ; CONN2.P1-23 81.94,21.4 ; CONN2.P1-23 80.99,20.46 ; CONN2.P1-23 82.88,20.46 ; CONN4.P1-21 212.56,20.46 ; CONN4.P1-21 211.62,19.52 ; CONN4.P1-21 211.62,21.4 ; CONN4.P1-21 210.67,20.46 ; 149.31,19.52 CONN3.P1-21 ; CONN3.P1-21 149.31,21.4 ; CONN3.P1-21 150.26,20.46 ; CONN3.P1-21 148.37,20.46 ; 28.85,20.46 CONN1.P1-12 ; CONN1.P1-12 29.79,21.4 ; CONN1.P1-12 29.79,19.52 ; CONN1.P1-12 30.74,20.46 ; CONN5.P1 330.14,12.65 ; CONN5.P1 328.95,11.46 ; CONN5.P1 328.95,13.84 ; CONN3.P1-12 155.34,20.46 ; CONN3.P1-12 153.45,20.46 ; CONN3.P1-12 154.39,19.52 ; CONN3.P1-12 154.39,21.4 ; 89.56,16.98 CONN2.P3-13 ; CONN2.P3-13 90.5,17.92 ; CONN2.P3-13 89.56,18.86 ; CONN2.P3-13 88.61,17.92 ; CONN1.P3-22 23.12,17.92 ; CONN1.P3-22 21.23,17.92 ; CONN1.P3-22 22.17,16.98 ; CONN1.P3-22 22.17,18.86 ; CONN3.P3-21 150.26,17.92 ; CONN3.P3-21 149.31,18.86 ; CONN3.P3-21 148.37,17.92 ; CONN3.P3-21 149.31,16.98 ; CONN4.P1-23 206.54,21.4 ; CONN4.P1-23 205.59,20.46 ; CONN4.P1-23 206.54,19.52 ; CONN4.P1-23 207.48,20.46 ; CONN3.P3-22 146.77,18.86 ; CONN3.P3-22 146.77,16.98 ; CONN3.P3-22 145.83,17.92 ; CONN3.P3-22 147.72,17.92 ; 143.29,20.46 CONN3.P1-23 ; CONN3.P1-23 145.18,20.46 ; CONN3.P1-23 144.23,21.4 ; CONN3.P1-23 144.23,19.52 ; 24.71,16.98 CONN1.P3-21 ; CONN1.P3-21 25.66,17.92 ; CONN1.P3-21 24.71,18.86 ; CONN1.P3-21 23.77,17.92 ; 81.94,16.98 CONN2.P3-23 ; CONN2.P3-23 81.94,18.86 ; CONN2.P3-23 82.88,17.92 ; CONN2.P3-23 80.99,17.92 ; 209.08,19.52 CONN4.P1-22 ; CONN4.P1-22 208.13,20.46 ; CONN4.P1-22 210.02,20.46 ; CONN4.P1-22 209.08,21.4 ; CONN4.P3-12 217.64,17.92 ; CONN4.P3-12 216.7,18.86 ; CONN4.P3-12 216.7,16.98 ; CONN4.P3-12 215.75,17.92 ; 26.31,20.46 CONN1.P1-13 ; CONN1.P1-13 27.25,19.52 ; CONN1.P1-13 27.25,21.4 ; CONN1.P1-13 28.2,20.46 ; CONN2.P3-12 92.1,18.86 ; CONN2.P3-12 92.1,16.98 ; CONN2.P3-12 91.15,17.92 ; CONN2.P3-12 93.04,17.92 ; 83.53,17.92 CONN2.P3-22 ; CONN2.P3-22 85.42,17.92 ; CONN2.P3-22 84.48,18.86 ; CONN2.P3-22 84.48,16.98 ; 155.99,17.92 CONN3.P3-11 ; CONN3.P3-11 156.93,18.86 ; CONN3.P3-11 157.88,17.92 ; CONN3.P3-11 156.93,16.98 ; CONN1.P3-12 29.79,18.86 ; CONN1.P3-12 30.74,17.92 ; CONN1.P3-12 28.85,17.92 ; CONN1.P3-12 29.79,16.98 ; CONN1.P1-23 19.63,21.4 ; CONN1.P1-23 20.58,20.46 ; CONN1.P1-23 18.69,20.46 ; CONN1.P1-23 19.63,19.52 ; CONN4.P3-21 211.62,18.86 ; CONN4.P3-21 212.56,17.92 ; CONN4.P3-21 210.67,17.92 ; CONN4.P3-21 211.62,16.98 ; 21.23,20.46 CONN1.P1-22 ; CONN1.P1-22 22.17,19.52 ; CONN1.P1-22 23.12,20.46 ; CONN1.P1-22 22.17,21.4 ; 23.77,20.46 CONN1.P1-21 ; CONN1.P1-21 24.71,19.52 ; CONN1.P1-21 25.66,20.46 ; CONN1.P1-21 24.71,21.4 ; CONN1.P3-13 27.25,18.86 ; CONN1.P3-13 26.31,17.92 ; CONN1.P3-13 27.25,16.98 ; CONN1.P3-13 28.2,17.92 ; CONN2.P1-12 92.1,21.4 ; CONN2.P1-12 93.04,20.46 ; CONN2.P1-12 91.15,20.46 ; CONN2.P1-12 92.1,19.52 ; 94.64,19.52 CONN2.P1-11 ; CONN2.P1-11 93.69,20.46 ; CONN2.P1-11 94.64,21.4 ; CONN2.P1-11 95.58,20.46 ; CONN4.P3-22 210.02,17.92 ; CONN4.P3-22 208.13,17.92 ; CONN4.P3-22 209.08,16.98 ; CONN4.P3-22 209.08,18.86 ; 31.39,20.46 CONN1.P1-11 ; CONN1.P1-11 33.28,20.46 ; CONN1.P1-11 32.33,19.52 ; CONN1.P1-11 32.33,21.4 ; 325.46,12.65 CONN5.P2 ; CONN5.P2 326.65,13.84 ; CONN5.P2 326.65,11.46 ; CONN3.P1-22 147.72,20.46 ; CONN3.P1-22 146.77,19.52 ; CONN3.P1-22 145.83,20.46 ; CONN3.P1-22 146.77,21.4 ; 156.93,19.52 CONN3.P1-11 ; CONN3.P1-11 155.99,20.46 ; CONN3.P1-11 157.88,20.46 ; CONN3.P1-11 156.93,21.4 ; 218.29,20.46 CONN4.P1-11 ; CONN4.P1-11 219.24,19.52 ; CONN4.P1-11 219.24,21.4 ; CONN4.P1-11 220.18,20.46 ; 89.56,19.52 CONN2.P1-13 ; CONN2.P1-13 89.56,21.4 ; CONN2.P1-13 90.5,20.46 ; CONN2.P1-13 88.61,20.46 ; 206.54,16.98 CONN4.P3-23 ; CONN4.P3-23 207.48,17.92 ; CONN4.P3-23 206.54,18.86 ; CONN4.P3-23 205.59,17.92 ; 143.29,17.92 CONN3.P3-23 ; CONN3.P3-23 144.23,18.86 ; CONN3.P3-23 144.23,16.98 ; CONN3.P3-23 145.18,17.92 ; 219.24,16.98 CONN4.P3-11 ; CONN4.P3-11 219.24,18.86 ; CONN4.P3-11 220.18,17.92 ; CONN4.P3-11 218.29,17.92 ; 154.39,16.98 CONN3.P3-12 ; CONN3.P3-12 155.34,17.92 ; CONN3.P3-12 154.39,18.86 ; CONN3.P3-12 153.45,17.92 ; CONN4.P1-13 215.1,20.46 ; CONN4.P1-13 214.16,19.52 ; CONN4.P1-13 214.16,21.4 ; CONN4.P1-13 213.21,20.46 ; 19.63,16.98 CONN1.P3-23 ; CONN1.P3-23 19.63,18.86 ; CONN1.P3-23 18.69,17.92 ; CONN1.P3-23 20.58,17.92 ; 93.69,17.92 CONN2.P3-11 ; CONN2.P3-11 94.64,16.98 ; CONN2.P3-11 94.64,18.86 ; CONN2.P3-11 95.58,17.92 ; CONN2.P1-22 85.42,20.46 ; CONN2.P1-22 84.48,19.52 ; CONN2.P1-22 84.48,21.4 ; CONN2.P1-22 83.53,20.46 ; 86.07,17.92 CONN2.P3-21 ; CONN2.P3-21 87.02,18.86 ; CONN2.P3-21 87.02,16.98 ; CONN2.P3-21 87.96,17.92 ; 151.85,16.98 CONN3.P3-13 ; CONN3.P3-13 152.8,17.92 ; CONN3.P3-13 151.85,18.86 ; CONN3.P3-13 150.91,17.92
  V14 w0.635: 32.33,19.52 CONN1.P1-11 ; CONN1.P1-11 31.39,20.46 ; CONN1.P1-11 32.33,21.4 ; CONN1.P1-11 33.28,20.46 ; CONN4.P1-12 216.7,21.4 ; CONN4.P1-12 216.7,19.52 ; CONN4.P1-12 217.64,20.46 ; CONN4.P1-12 215.75,20.46 ; CONN1.P3-13 28.2,17.92 ; CONN1.P3-13 27.25,18.86 ; CONN1.P3-13 27.25,16.98 ; CONN1.P3-13 26.31,17.92 ; 153.45,17.92 CONN3.P3-12 ; CONN3.P3-12 154.39,16.98 ; CONN3.P3-12 154.39,18.86 ; CONN3.P3-12 155.34,17.92 ; 91.15,17.92 CONN2.P3-12 ; CONN2.P3-12 92.1,16.98 ; CONN2.P3-12 92.1,18.86 ; CONN2.P3-12 93.04,17.92 ; 93.69,17.92 CONN2.P3-11 ; CONN2.P3-11 94.64,16.98 ; CONN2.P3-11 94.64,18.86 ; CONN2.P3-11 95.58,17.92 ; 86.07,17.92 CONN2.P3-21 ; CONN2.P3-21 87.96,17.92 ; CONN2.P3-21 87.02,18.86 ; CONN2.P3-21 87.02,16.98 ; CONN3.P1-12 154.39,21.4 ; CONN3.P1-12 155.34,20.46 ; CONN3.P1-12 154.39,19.52 ; CONN3.P1-12 153.45,20.46 ; CONN4.P3-21 211.62,18.86 ; CONN4.P3-21 210.67,17.92 ; CONN4.P3-21 211.62,16.98 ; CONN4.P3-21 212.56,17.92 ; 149.31,16.98 CONN3.P3-21 ; CONN3.P3-21 149.31,18.86 ; CONN3.P3-21 148.37,17.92 ; CONN3.P3-21 150.26,17.92 ; 205.59,17.92 CONN4.P3-23 ; CONN4.P3-23 206.54,16.98 ; CONN4.P3-23 207.48,17.92 ; CONN4.P3-23 206.54,18.86 ; 31.39,17.92 CONN1.P3-11 ; CONN1.P3-11 32.33,18.86 ; CONN1.P3-11 32.33,16.98 ; CONN1.P3-11 33.28,17.92 ; CONN4.P1-11 219.24,21.4 ; CONN4.P1-11 219.24,19.52 ; CONN4.P1-11 218.29,20.46 ; CONN4.P1-11 220.18,20.46 ; CONN4.P3-11 219.24,18.86 ; CONN4.P3-11 218.29,17.92 ; CONN4.P3-11 219.24,16.98 ; CONN4.P3-11 220.18,17.92 ; 325.46,12.65 CONN5.P2 ; CONN5.P2 326.65,11.46 ; CONN5.P2 326.65,13.84 ; CONN2.P1-13 89.56,21.4 ; CONN2.P1-13 90.5,20.46 ; CONN2.P1-13 89.56,19.52 ; CONN2.P1-13 88.61,20.46 ; 80.99,20.46 CONN2.P1-23 ; CONN2.P1-23 82.88,20.46 ; CONN2.P1-23 81.94,19.52 ; CONN2.P1-23 81.94,21.4 ; 216.7,16.98 CONN4.P3-12 ; CONN4.P3-12 217.64,17.92 ; CONN4.P3-12 215.75,17.92 ; CONN4.P3-12 216.7,18.86 ; 151.85,16.98 CONN3.P3-13 ; CONN3.P3-13 152.8,17.92 ; CONN3.P3-13 150.91,17.92 ; CONN3.P3-13 151.85,18.86 ; CONN2.P3-23 81.94,18.86 ; CONN2.P3-23 81.94,16.98 ; CONN2.P3-23 82.88,17.92 ; CONN2.P3-23 80.99,17.92 ; CONN3.P3-22 147.72,17.92 ; CONN3.P3-22 145.83,17.92 ; CONN3.P3-22 146.77,16.98 ; CONN3.P3-22 146.77,18.86 ; 29.79,16.98 CONN1.P3-12 ; CONN1.P3-12 28.85,17.92 ; CONN1.P3-12 30.74,17.92 ; CONN1.P3-12 29.79,18.86 ; 155.99,20.46 CONN3.P1-11 ; CONN3.P1-11 157.88,20.46 ; CONN3.P1-11 156.93,21.4 ; CONN3.P1-11 156.93,19.52 ; 19.63,19.52 CONN1.P1-23 ; CONN1.P1-23 20.58,20.46 ; CONN1.P1-23 18.69,20.46 ; CONN1.P1-23 19.63,21.4 ; 155.99,17.92 CONN3.P3-11 ; CONN3.P3-11 156.93,18.86 ; CONN3.P3-11 156.93,16.98 ; CONN3.P3-11 157.88,17.92 ; CONN2.P1-22 84.48,21.4 ; CONN2.P1-22 83.53,20.46 ; CONN2.P1-22 84.48,19.52 ; CONN2.P1-22 85.42,20.46 ; 94.64,19.52 CONN2.P1-11 ; CONN2.P1-11 93.69,20.46 ; CONN2.P1-11 94.64,21.4 ; CONN2.P1-11 95.58,20.46 ; CONN1.P3-21 24.71,18.86 ; CONN1.P3-21 23.77,17.92 ; CONN1.P3-21 25.66,17.92 ; CONN1.P3-21 24.71,16.98 ; CONN2.P3-22 84.48,18.86 ; CONN2.P3-22 84.48,16.98 ; CONN2.P3-22 85.42,17.92 ; CONN2.P3-22 83.53,17.92 ; CONN2.P3-13 89.56,18.86 ; CONN2.P3-13 90.5,17.92 ; CONN2.P3-13 89.56,16.98 ; CONN2.P3-13 88.61,17.92 ; 146.77,19.52 CONN3.P1-22 ; CONN3.P1-22 146.77,21.4 ; CONN3.P1-22 145.83,20.46 ; CONN3.P1-22 147.72,20.46 ; 27.25,19.52 CONN1.P1-13 ; CONN1.P1-13 27.25,21.4 ; CONN1.P1-13 28.2,20.46 ; CONN1.P1-13 26.31,20.46 ; 24.71,19.52 CONN1.P1-21 ; CONN1.P1-21 25.66,20.46 ; CONN1.P1-21 23.77,20.46 ; CONN1.P1-21 24.71,21.4 ; 214.16,19.52 CONN4.P1-13 ; CONN4.P1-13 215.1,20.46 ; CONN4.P1-13 214.16,21.4 ; CONN4.P1-13 213.21,20.46 ; 149.31,19.52 CONN3.P1-21 ; CONN3.P1-21 150.26,20.46 ; CONN3.P1-21 148.37,20.46 ; CONN3.P1-21 149.31,21.4 ; 21.23,20.46 CONN1.P1-22 ; CONN1.P1-22 22.17,21.4 ; CONN1.P1-22 22.17,19.52 ; CONN1.P1-22 23.12,20.46 ; 208.13,20.46 CONN4.P1-22 ; CONN4.P1-22 209.08,21.4 ; CONN4.P1-22 210.02,20.46 ; CONN4.P1-22 209.08,19.52 ; CONN3.P3-23 144.23,18.86 ; CONN3.P3-23 144.23,16.98 ; CONN3.P3-23 143.29,17.92 ; CONN3.P3-23 145.18,17.92 ; CONN5.P1 328.95,13.84 ; CONN5.P1 330.14,12.65 ; CONN5.P1 328.95,11.46 ; 144.23,19.52 CONN3.P1-23 ; CONN3.P1-23 144.23,21.4 ; CONN3.P1-23 143.29,20.46 ; CONN3.P1-23 145.18,20.46 ; 208.13,17.92 CONN4.P3-22 ; CONN4.P3-22 209.08,18.86 ; CONN4.P3-22 209.08,16.98 ; CONN4.P3-22 210.02,17.92 ; CONN4.P1-23 207.48,20.46 ; CONN4.P1-23 206.54,21.4 ; CONN4.P1-23 205.59,20.46 ; CONN4.P1-23 206.54,19.52 ; CONN2.P1-21 87.02,21.4 ; CONN2.P1-21 87.96,20.46 ; CONN2.P1-21 87.02,19.52 ; CONN2.P1-21 86.07,20.46 ; 211.62,19.52 CONN4.P1-21 ; CONN4.P1-21 212.56,20.46 ; CONN4.P1-21 210.67,20.46 ; CONN4.P1-21 211.62,21.4 ; CONN4.P3-13 215.1,17.92 ; CONN4.P3-13 214.16,18.86 ; CONN4.P3-13 213.21,17.92 ; CONN4.P3-13 214.16,16.98 ; CONN1.P3-22 22.17,18.86 ; CONN1.P3-22 21.23,17.92 ; CONN1.P3-22 22.17,16.98 ; CONN1.P3-22 23.12,17.92 ; 150.91,20.46 CONN3.P1-13 ; CONN3.P1-13 152.8,20.46 ; CONN3.P1-13 151.85,21.4 ; CONN3.P1-13 151.85,19.52 ; 29.79,19.52 CONN1.P1-12 ; CONN1.P1-12 29.79,21.4 ; CONN1.P1-12 30.74,20.46 ; CONN1.P1-12 28.85,20.46 ; 91.15,20.46 CONN2.P1-12 ; CONN2.P1-12 92.1,21.4 ; CONN2.P1-12 92.1,19.52 ; CONN2.P1-12 93.04,20.46 ; 18.69,17.92 CONN1.P3-23 ; CONN1.P3-23 19.63,18.86 ; CONN1.P3-23 19.63,16.98 ; CONN1.P3-23 20.58,17.92
  V16 w0.635: CONN4.P3-13 215.1,17.92 ; CONN4.P3-13 213.21,17.92 ; CONN4.P3-13 214.16,16.98 ; CONN4.P3-13 214.16,18.86 ; 22.17,19.52 CONN1.P1-22 ; CONN1.P1-22 21.23,20.46 ; CONN1.P1-22 23.12,20.46 ; CONN1.P1-22 22.17,21.4 ; 219.24,19.52 CONN4.P1-11 ; CONN4.P1-11 219.24,21.4 ; CONN4.P1-11 220.18,20.46 ; CONN4.P1-11 218.29,20.46 ; CONN2.P1-22 85.42,20.46 ; CONN2.P1-22 84.48,19.52 ; CONN2.P1-22 84.48,21.4 ; CONN2.P1-22 83.53,20.46 ; CONN2.P3-13 90.5,17.92 ; CONN2.P3-13 89.56,16.98 ; CONN2.P3-13 89.56,18.86 ; CONN2.P3-13 88.61,17.92 ; CONN1.P1-23 19.63,21.4 ; CONN1.P1-23 18.69,20.46 ; CONN1.P1-23 20.58,20.46 ; CONN1.P1-23 19.63,19.52 ; 24.71,16.98 CONN1.P3-21 ; CONN1.P3-21 25.66,17.92 ; CONN1.P3-21 23.77,17.92 ; CONN1.P3-21 24.71,18.86 ; CONN3.P3-21 150.26,17.92 ; CONN3.P3-21 149.31,18.86 ; CONN3.P3-21 148.37,17.92 ; CONN3.P3-21 149.31,16.98 ; CONN4.P3-21 212.56,17.92 ; CONN4.P3-21 211.62,16.98 ; CONN4.P3-21 210.67,17.92 ; CONN4.P3-21 211.62,18.86 ; 80.99,20.46 CONN2.P1-23 ; CONN2.P1-23 81.94,21.4 ; CONN2.P1-23 82.88,20.46 ; CONN2.P1-23 81.94,19.52 ; 153.45,20.46 CONN3.P1-12 ; CONN3.P1-12 155.34,20.46 ; CONN3.P1-12 154.39,19.52 ; CONN3.P1-12 154.39,21.4 ; 88.61,20.46 CONN2.P1-13 ; CONN2.P1-13 90.5,20.46 ; CONN2.P1-13 89.56,21.4 ; CONN2.P1-13 89.56,19.52 ; CONN2.P1-21 87.96,20.46 ; CONN2.P1-21 87.02,19.52 ; CONN2.P1-21 86.07,20.46 ; CONN2.P1-21 87.02,21.4 ; CONN2.P3-21 87.02,18.86 ; CONN2.P3-21 86.07,17.92 ; CONN2.P3-21 87.96,17.92 ; CONN2.P3-21 87.02,16.98 ; CONN1.P1-21 24.71,21.4 ; CONN1.P1-21 25.66,20.46 ; CONN1.P1-21 23.77,20.46 ; CONN1.P1-21 24.71,19.52 ; 206.54,16.98 CONN4.P3-23 ; CONN4.P3-23 205.59,17.92 ; CONN4.P3-23 207.48,17.92 ; CONN4.P3-23 206.54,18.86 ; CONN1.P1-13 28.2,20.46 ; CONN1.P1-13 26.31,20.46 ; CONN1.P1-13 27.25,21.4 ; CONN1.P1-13 27.25,19.52 ; 151.85,16.98 CONN3.P3-13 ; CONN3.P3-13 152.8,17.92 ; CONN3.P3-13 151.85,18.86 ; CONN3.P3-13 150.91,17.92 ; 155.99,20.46 CONN3.P1-11 ; CONN3.P1-11 156.93,19.52 ; CONN3.P1-11 157.88,20.46 ; CONN3.P1-11 156.93,21.4 ; CONN2.P3-12 92.1,18.86 ; CONN2.P3-12 92.1,16.98 ; CONN2.P3-12 91.15,17.92 ; CONN2.P3-12 93.04,17.92 ; CONN4.P1-12 217.64,20.46 ; CONN4.P1-12 216.7,21.4 ; CONN4.P1-12 216.7,19.52 ; CONN4.P1-12 215.75,20.46 ; 208.13,17.92 CONN4.P3-22 ; CONN4.P3-22 209.08,18.86 ; CONN4.P3-22 209.08,16.98 ; CONN4.P3-22 210.02,17.92 ; 326.65,11.46 CONN5.P2 ; CONN5.P2 325.46,12.65 ; CONN5.P2 326.65,13.84 ; CONN3.P1-21 149.31,21.4 ; CONN3.P1-21 150.26,20.46 ; CONN3.P1-21 148.37,20.46 ; CONN3.P1-21 149.31,19.52 ; CONN4.P3-11 219.24,18.86 ; CONN4.P3-11 219.24,16.98 ; CONN4.P3-11 220.18,17.92 ; CONN4.P3-11 218.29,17.92 ; 84.48,16.98 CONN2.P3-22 ; CONN2.P3-22 84.48,18.86 ; CONN2.P3-22 83.53,17.92 ; CONN2.P3-22 85.42,17.92 ; 32.33,16.98 CONN1.P3-11 ; CONN1.P3-11 32.33,18.86 ; CONN1.P3-11 33.28,17.92 ; CONN1.P3-11 31.39,17.92 ; 209.08,19.52 CONN4.P1-22 ; CONN4.P1-22 210.02,20.46 ; CONN4.P1-22 209.08,21.4 ; CONN4.P1-22 208.13,20.46 ; 145.83,17.92 CONN3.P3-22 ; CONN3.P3-22 146.77,18.86 ; CONN3.P3-22 147.72,17.92 ; CONN3.P3-22 146.77,16.98 ; CONN4.P1-21 212.56,20.46 ; CONN4.P1-21 211.62,21.4 ; CONN4.P1-21 211.62,19.52 ; CONN4.P1-21 210.67,20.46 ; 205.59,20.46 CONN4.P1-23 ; CONN4.P1-23 206.54,19.52 ; CONN4.P1-23 206.54,21.4 ; CONN4.P1-23 207.48,20.46 ; CONN1.P3-22 23.12,17.92 ; CONN1.P3-22 22.17,18.86 ; CONN1.P3-22 21.23,17.92 ; CONN1.P3-22 22.17,16.98 ; 93.69,17.92 CONN2.P3-11 ; CONN2.P3-11 94.64,18.86 ; CONN2.P3-11 95.58,17.92 ; CONN2.P3-11 94.64,16.98 ; 328.95,11.46 CONN5.P1 ; CONN5.P1 330.14,12.65 ; CONN5.P1 328.95,13.84 ; 28.85,20.46 CONN1.P1-12 ; CONN1.P1-12 29.79,19.52 ; CONN1.P1-12 29.79,21.4 ; CONN1.P1-12 30.74,20.46 ; CONN1.P1-11 33.28,20.46 ; CONN1.P1-11 31.39,20.46 ; CONN1.P1-11 32.33,19.52 ; CONN1.P1-11 32.33,21.4 ; 19.63,16.98 CONN1.P3-23 ; CONN1.P3-23 19.63,18.86 ; CONN1.P3-23 20.58,17.92 ; CONN1.P3-23 18.69,17.92 ; 81.94,16.98 CONN2.P3-23 ; CONN2.P3-23 82.88,17.92 ; CONN2.P3-23 80.99,17.92 ; CONN2.P3-23 81.94,18.86 ; CONN1.P3-13 27.25,18.86 ; CONN1.P3-13 28.2,17.92 ; CONN1.P3-13 26.31,17.92 ; CONN1.P3-13 27.25,16.98 ; 154.39,16.98 CONN3.P3-12 ; CONN3.P3-12 153.45,17.92 ; CONN3.P3-12 155.34,17.92 ; CONN3.P3-12 154.39,18.86 ; 156.93,16.98 CONN3.P3-11 ; CONN3.P3-11 155.99,17.92 ; CONN3.P3-11 157.88,17.92 ; CONN3.P3-11 156.93,18.86 ; 213.21,20.46 CONN4.P1-13 ; CONN4.P1-13 214.16,19.52 ; CONN4.P1-13 215.1,20.46 ; CONN4.P1-13 214.16,21.4 ; 143.29,20.46 CONN3.P1-23 ; CONN3.P1-23 144.23,21.4 ; CONN3.P1-23 145.18,20.46 ; CONN3.P1-23 144.23,19.52 ; CONN3.P1-22 147.72,20.46 ; CONN3.P1-22 146.77,19.52 ; CONN3.P1-22 146.77,21.4 ; CONN3.P1-22 145.83,20.46 ; CONN3.P1-13 151.85,21.4 ; CONN3.P1-13 150.91,20.46 ; CONN3.P1-13 151.85,19.52 ; CONN3.P1-13 152.8,20.46 ; CONN1.P3-12 29.79,18.86 ; CONN1.P3-12 28.85,17.92 ; CONN1.P3-12 30.74,17.92 ; CONN1.P3-12 29.79,16.98 ; CONN2.P1-11 95.58,20.46 ; CONN2.P1-11 93.69,20.46 ; CONN2.P1-11 94.64,21.4 ; CONN2.P1-11 94.64,19.52 ; 216.7,16.98 CONN4.P3-12 ; CONN4.P3-12 216.7,18.86 ; CONN4.P3-12 215.75,17.92 ; CONN4.P3-12 217.64,17.92 ; 91.15,20.46 CONN2.P1-12 ; CONN2.P1-12 92.1,21.4 ; CONN2.P1-12 93.04,20.46 ; CONN2.P1-12 92.1,19.52 ; 144.23,16.98 CONN3.P3-23 ; CONN3.P3-23 144.23,18.86 ; CONN3.P3-23 143.29,17.92 ; CONN3.P3-23 145.18,17.92
  V18 w0.635: 28.85,20.46 CONN1.P1-12 ; CONN1.P1-12 29.79,21.4 ; CONN1.P1-12 29.79,19.52 ; CONN1.P1-12 30.74,20.46 ; CONN1.P1-11 33.28,20.46 ; CONN1.P1-11 32.33,19.52 ; CONN1.P1-11 32.33,21.4 ; CONN1.P1-11 31.39,20.46 ; 156.93,16.98 CONN3.P3-11 ; CONN3.P3-11 155.99,17.92 ; CONN3.P3-11 156.93,18.86 ; CONN3.P3-11 157.88,17.92 ; 92.1,16.98 CONN2.P3-12 ; CONN2.P3-12 92.1,18.86 ; CONN2.P3-12 93.04,17.92 ; CONN2.P3-12 91.15,17.92 ; CONN1.P3-13 28.2,17.92 ; CONN1.P3-13 27.25,16.98 ; CONN1.P3-13 26.31,17.92 ; CONN1.P3-13 27.25,18.86 ; 208.13,20.46 CONN4.P1-22 ; CONN4.P1-22 210.02,20.46 ; CONN4.P1-22 209.08,21.4 ; CONN4.P1-22 209.08,19.52 ; CONN2.P3-23 82.88,17.92 ; CONN2.P3-23 81.94,18.86 ; CONN2.P3-23 80.99,17.92 ; CONN2.P3-23 81.94,16.98 ; 18.69,20.46 CONN1.P1-23 ; CONN1.P1-23 20.58,20.46 ; CONN1.P1-23 19.63,19.52 ; CONN1.P1-23 19.63,21.4 ; 208.13,17.92 CONN4.P3-22 ; CONN4.P3-22 209.08,18.86 ; CONN4.P3-22 209.08,16.98 ; CONN4.P3-22 210.02,17.92 ; 210.67,20.46 CONN4.P1-21 ; CONN4.P1-21 211.62,19.52 ; CONN4.P1-21 212.56,20.46 ; CONN4.P1-21 211.62,21.4 ; 153.45,20.46 CONN3.P1-12 ; CONN3.P1-12 155.34,20.46 ; CONN3.P1-12 154.39,21.4 ; CONN3.P1-12 154.39,19.52 ; 84.48,16.98 CONN2.P3-22 ; CONN2.P3-22 85.42,17.92 ; CONN2.P3-22 83.53,17.92 ; CONN2.P3-22 84.48,18.86 ; 89.56,19.52 CONN2.P1-13 ; CONN2.P1-13 88.61,20.46 ; CONN2.P1-13 89.56,21.4 ; CONN2.P1-13 90.5,20.46 ; 214.16,19.52 CONN4.P1-13 ; CONN4.P1-13 214.16,21.4 ; CONN4.P1-13 215.1,20.46 ; CONN4.P1-13 213.21,20.46 ; 148.37,20.46 CONN3.P1-21 ; CONN3.P1-21 149.31,21.4 ; CONN3.P1-21 150.26,20.46 ; CONN3.P1-21 149.31,19.52 ; CONN4.P3-12 216.7,18.86 ; CONN4.P3-12 216.7,16.98 ; CONN4.P3-12 217.64,17.92 ; CONN4.P3-12 215.75,17.92 ; 91.15,20.46 CONN2.P1-12 ; CONN2.P1-12 92.1,21.4 ; CONN2.P1-12 93.04,20.46 ; CONN2.P1-12 92.1,19.52 ; 143.29,17.92 CONN3.P3-23 ; CONN3.P3-23 144.23,16.98 ; CONN3.P3-23 144.23,18.86 ; CONN3.P3-23 145.18,17.92 ; 149.31,16.98 CONN3.P3-21 ; CONN3.P3-21 150.26,17.92 ; CONN3.P3-21 149.31,18.86 ; CONN3.P3-21 148.37,17.92 ; 27.25,19.52 CONN1.P1-13 ; CONN1.P1-13 27.25,21.4 ; CONN1.P1-13 28.2,20.46 ; CONN1.P1-13 26.31,20.46 ; CONN1.P1-21 25.66,20.46 ; CONN1.P1-21 24.71,21.4 ; CONN1.P1-21 23.77,20.46 ; CONN1.P1-21 24.71,19.52 ; 145.83,17.92 CONN3.P3-22 ; CONN3.P3-22 147.72,17.92 ; CONN3.P3-22 146.77,16.98 ; CONN3.P3-22 146.77,18.86 ; CONN3.P1-13 151.85,21.4 ; CONN3.P1-13 150.91,20.46 ; CONN3.P1-13 151.85,19.52 ; CONN3.P1-13 152.8,20.46 ; 87.02,19.52 CONN2.P1-21 ; CONN2.P1-21 86.07,20.46 ; CONN2.P1-21 87.96,20.46 ; CONN2.P1-21 87.02,21.4 ; 21.23,17.92 CONN1.P3-22 ; CONN1.P3-22 22.17,18.86 ; CONN1.P3-22 23.12,17.92 ; CONN1.P3-22 22.17,16.98 ; CONN2.P1-11 94.64,21.4 ; CONN2.P1-11 93.69,20.46 ; CONN2.P1-11 94.64,19.52 ; CONN2.P1-11 95.58,20.46 ; 219.24,16.98 CONN4.P3-11 ; CONN4.P3-11 219.24,18.86 ; CONN4.P3-11 218.29,17.92 ; CONN4.P3-11 220.18,17.92 ; 206.54,16.98 CONN4.P3-23 ; CONN4.P3-23 206.54,18.86 ; CONN4.P3-23 205.59,17.92 ; CONN4.P3-23 207.48,17.92 ; 18.69,17.92 CONN1.P3-23 ; CONN1.P3-23 20.58,17.92 ; CONN1.P3-23 19.63,16.98 ; CONN1.P3-23 19.63,18.86 ; 23.77,17.92 CONN1.P3-21 ; CONN1.P3-21 24.71,18.86 ; CONN1.P3-21 25.66,17.92 ; CONN1.P3-21 24.71,16.98 ; 81.94,19.52 CONN2.P1-23 ; CONN2.P1-23 80.99,20.46 ; CONN2.P1-23 81.94,21.4 ; CONN2.P1-23 82.88,20.46 ; 205.59,20.46 CONN4.P1-23 ; CONN4.P1-23 206.54,21.4 ; CONN4.P1-23 207.48,20.46 ; CONN4.P1-23 206.54,19.52 ; CONN4.P1-11 219.24,21.4 ; CONN4.P1-11 219.24,19.52 ; CONN4.P1-11 218.29,20.46 ; CONN4.P1-11 220.18,20.46 ; 156.93,19.52 CONN3.P1-11 ; CONN3.P1-11 155.99,20.46 ; CONN3.P1-11 157.88,20.46 ; CONN3.P1-11 156.93,21.4 ; CONN3.P3-12 154.39,18.86 ; CONN3.P3-12 153.45,17.92 ; CONN3.P3-12 154.39,16.98 ; CONN3.P3-12 155.34,17.92 ; CONN2.P1-22 85.42,20.46 ; CONN2.P1-22 83.53,20.46 ; CONN2.P1-22 84.48,21.4 ; CONN2.P1-22 84.48,19.52 ; 146.77,19.52 CONN3.P1-22 ; CONN3.P1-22 146.77,21.4 ; CONN3.P1-22 147.72,20.46 ; CONN3.P1-22 145.83,20.46 ; 210.67,17.92 CONN4.P3-21 ; CONN4.P3-21 211.62,16.98 ; CONN4.P3-21 212.56,17.92 ; CONN4.P3-21 211.62,18.86 ; CONN4.P3-13 215.1,17.92 ; CONN4.P3-13 214.16,16.98 ; CONN4.P3-13 214.16,18.86 ; CONN4.P3-13 213.21,17.92 ; CONN2.P3-11 95.58,17.92 ; CONN2.P3-11 94.64,16.98 ; CONN2.P3-11 93.69,17.92 ; CONN2.P3-11 94.64,18.86 ; 89.56,16.98 CONN2.P3-13 ; CONN2.P3-13 89.56,18.86 ; CONN2.P3-13 88.61,17.92 ; CONN2.P3-13 90.5,17.92 ; CONN4.P1-12 216.7,21.4 ; CONN4.P1-12 215.75,20.46 ; CONN4.P1-12 217.64,20.46 ; CONN4.P1-12 216.7,19.52 ; CONN3.P3-13 152.8,17.92 ; CONN3.P3-13 150.91,17.92 ; CONN3.P3-13 151.85,16.98 ; CONN3.P3-13 151.85,18.86 ; CONN1.P3-12 29.79,18.86 ; CONN1.P3-12 29.79,16.98 ; CONN1.P3-12 28.85,17.92 ; CONN1.P3-12 30.74,17.92 ; 21.23,20.46 CONN1.P1-22 ; CONN1.P1-22 23.12,20.46 ; CONN1.P1-22 22.17,21.4 ; CONN1.P1-22 22.17,19.52 ; CONN5.P1 328.95,13.84 ; CONN5.P1 328.95,11.46 ; CONN5.P1 330.14,12.65 ; CONN3.P1-23 144.23,21.4 ; CONN3.P1-23 144.23,19.52 ; CONN3.P1-23 145.18,20.46 ; CONN3.P1-23 143.29,20.46 ; 86.07,17.92 CONN2.P3-21 ; CONN2.P3-21 87.02,18.86 ; CONN2.P3-21 87.02,16.98 ; CONN2.P3-21 87.96,17.92 ; CONN1.P3-11 32.33,18.86 ; CONN1.P3-11 31.39,17.92 ; CONN1.P3-11 33.28,17.92 ; CONN1.P3-11 32.33,16.98 ; 325.46,12.65 CONN5.P2 ; CONN5.P2 326.65,11.46 ; CONN5.P2 326.65,13.84
  V20 w0.635: 326.65,11.46 CONN5.P2 ; CONN5.P2 325.46,12.65 ; CONN5.P2 326.65,13.84 ; 151.85,19.52 CONN3.P1-13 ; CONN3.P1-13 151.85,21.4 ; CONN3.P1-13 152.8,20.46 ; CONN3.P1-13 150.91,20.46 ; 216.7,19.52 CONN4.P1-12 ; CONN4.P1-12 217.64,20.46 ; CONN4.P1-12 216.7,21.4 ; CONN4.P1-12 215.75,20.46 ; CONN2.P1-11 95.58,20.46 ; CONN2.P1-11 94.64,21.4 ; CONN2.P1-11 93.69,20.46 ; CONN2.P1-11 94.64,19.52 ; 92.1,19.52 CONN2.P1-12 ; CONN2.P1-12 93.04,20.46 ; CONN2.P1-12 91.15,20.46 ; CONN2.P1-12 92.1,21.4 ; 155.99,17.92 CONN3.P3-11 ; CONN3.P3-11 157.88,17.92 ; CONN3.P3-11 156.93,18.86 ; CONN3.P3-11 156.93,16.98 ; CONN2.P1-23 81.94,21.4 ; CONN2.P1-23 81.94,19.52 ; CONN2.P1-23 80.99,20.46 ; CONN2.P1-23 82.88,20.46 ; 29.79,19.52 CONN1.P1-12 ; CONN1.P1-12 28.85,20.46 ; CONN1.P1-12 30.74,20.46 ; CONN1.P1-12 29.79,21.4 ; CONN4.P3-13 214.16,18.86 ; CONN4.P3-13 214.16,16.98 ; CONN4.P3-13 213.21,17.92 ; CONN4.P3-13 215.1,17.92 ; 22.17,19.52 CONN1.P1-22 ; CONN1.P1-22 21.23,20.46 ; CONN1.P1-22 23.12,20.46 ; CONN1.P1-22 22.17,21.4 ; 27.25,16.98 CONN1.P3-13 ; CONN1.P3-13 26.31,17.92 ; CONN1.P3-13 27.25,18.86 ; CONN1.P3-13 28.2,17.92 ; CONN3.P1-12 155.34,20.46 ; CONN3.P1-12 153.45,20.46 ; CONN3.P1-12 154.39,19.52 ; CONN3.P1-12 154.39,21.4 ; CONN1.P1-21 24.71,21.4 ; CONN1.P1-21 24.71,19.52 ; CONN1.P1-21 23.77,20.46 ; CONN1.P1-21 25.66,20.46 ; 31.39,20.46 CONN1.P1-11 ; CONN1.P1-11 33.28,20.46 ; CONN1.P1-11 32.33,21.4 ; CONN1.P1-11 32.33,19.52 ; CONN3.P3-21 149.31,18.86 ; CONN3.P3-21 148.37,17.92 ; CONN3.P3-21 150.26,17.92 ; CONN3.P3-21 149.31,16.98 ; 23.77,17.92 CONN1.P3-21 ; CONN1.P3-21 25.66,17.92 ; CONN1.P3-21 24.71,16.98 ; CONN1.P3-21 24.71,18.86 ; 88.61,17.92 CONN2.P3-13 ; CONN2.P3-13 89.56,18.86 ; CONN2.P3-13 89.56,16.98 ; CONN2.P3-13 90.5,17.92 ; 213.21,20.46 CONN4.P1-13 ; CONN4.P1-13 215.1,20.46 ; CONN4.P1-13 214.16,21.4 ; CONN4.P1-13 214.16,19.52 ; CONN3.P3-22 147.72,17.92 ; CONN3.P3-22 146.77,16.98 ; CONN3.P3-22 145.83,17.92 ; CONN3.P3-22 146.77,18.86 ; 206.54,19.52 CONN4.P1-23 ; CONN4.P1-23 205.59,20.46 ; CONN4.P1-23 207.48,20.46 ; CONN4.P1-23 206.54,21.4 ; CONN2.P1-22 85.42,20.46 ; CONN2.P1-22 83.53,20.46 ; CONN2.P1-22 84.48,19.52 ; CONN2.P1-22 84.48,21.4 ; 29.79,16.98 CONN1.P3-12 ; CONN1.P3-12 30.74,17.92 ; CONN1.P3-12 28.85,17.92 ; CONN1.P3-12 29.79,18.86 ; CONN4.P3-12 216.7,18.86 ; CONN4.P3-12 217.64,17.92 ; CONN4.P3-12 215.75,17.92 ; CONN4.P3-12 216.7,16.98 ; CONN3.P3-13 152.8,17.92 ; CONN3.P3-13 151.85,16.98 ; CONN3.P3-13 150.91,17.92 ; CONN3.P3-13 151.85,18.86 ; 88.61,20.46 CONN2.P1-13 ; CONN2.P1-13 89.56,19.52 ; CONN2.P1-13 90.5,20.46 ; CONN2.P1-13 89.56,21.4 ; 91.15,17.92 CONN2.P3-12 ; CONN2.P3-12 92.1,16.98 ; CONN2.P3-12 92.1,18.86 ; CONN2.P3-12 93.04,17.92 ; CONN5.P1 328.95,13.84 ; CONN5.P1 328.95,11.46 ; CONN5.P1 330.14,12.65 ; CONN4.P3-23 207.48,17.92 ; CONN4.P3-23 206.54,18.86 ; CONN4.P3-23 206.54,16.98 ; CONN4.P3-23 205.59,17.92 ; CONN1.P1-23 20.58,20.46 ; CONN1.P1-23 18.69,20.46 ; CONN1.P1-23 19.63,21.4 ; CONN1.P1-23 19.63,19.52 ; 86.07,20.46 CONN2.P1-21 ; CONN2.P1-21 87.02,21.4 ; CONN2.P1-21 87.96,20.46 ; CONN2.P1-21 87.02,19.52 ; CONN3.P1-22 146.77,21.4 ; CONN3.P1-22 145.83,20.46 ; CONN3.P1-22 146.77,19.52 ; CONN3.P1-22 147.72,20.46 ; CONN4.P1-22 210.02,20.46 ; CONN4.P1-22 209.08,21.4 ; CONN4.P1-22 209.08,19.52 ; CONN4.P1-22 208.13,20.46 ; 219.24,19.52 CONN4.P1-11 ; CONN4.P1-11 220.18,20.46 ; CONN4.P1-11 218.29,20.46 ; CONN4.P1-11 219.24,21.4 ; 149.31,19.52 CONN3.P1-21 ; CONN3.P1-21 149.31,21.4 ; CONN3.P1-21 150.26,20.46 ; CONN3.P1-21 148.37,20.46 ; CONN1.P3-11 33.28,17.92 ; CONN1.P3-11 32.33,16.98 ; CONN1.P3-11 31.39,17.92 ; CONN1.P3-11 32.33,18.86 ; 87.02,16.98 CONN2.P3-21 ; CONN2.P3-21 86.07,17.92 ; CONN2.P3-21 87.96,17.92 ; CONN2.P3-21 87.02,18.86 ; 27.25,19.52 CONN1.P1-13 ; CONN1.P1-13 27.25,21.4 ; CONN1.P1-13 26.31,20.46 ; CONN1.P1-13 28.2,20.46 ; CONN3.P1-11 156.93,21.4 ; CONN3.P1-11 156.93,19.52 ; CONN3.P1-11 155.99,20.46 ; CONN3.P1-11 157.88,20.46 ; 84.48,16.98 CONN2.P3-22 ; CONN2.P3-22 85.42,17.92 ; CONN2.P3-22 84.48,18.86 ; CONN2.P3-22 83.53,17.92 ; 143.29,20.46 CONN3.P1-23 ; CONN3.P1-23 144.23,21.4 ; CONN3.P1-23 145.18,20.46 ; CONN3.P1-23 144.23,19.52 ; 22.17,16.98 CONN1.P3-22 ; CONN1.P3-22 22.17,18.86 ; CONN1.P3-22 21.23,17.92 ; CONN1.P3-22 23.12,17.92 ; CONN1.P3-23 19.63,18.86 ; CONN1.P3-23 18.69,17.92 ; CONN1.P3-23 19.63,16.98 ; CONN1.P3-23 20.58,17.92 ; CONN4.P3-21 212.56,17.92 ; CONN4.P3-21 211.62,16.98 ; CONN4.P3-21 211.62,18.86 ; CONN4.P3-21 210.67,17.92 ; 81.94,16.98 CONN2.P3-23 ; CONN2.P3-23 80.99,17.92 ; CONN2.P3-23 82.88,17.92 ; CONN2.P3-23 81.94,18.86 ; 154.39,16.98 CONN3.P3-12 ; CONN3.P3-12 154.39,18.86 ; CONN3.P3-12 155.34,17.92 ; CONN3.P3-12 153.45,17.92 ; CONN3.P3-23 145.18,17.92 ; CONN3.P3-23 143.29,17.92 ; CONN3.P3-23 144.23,18.86 ; CONN3.P3-23 144.23,16.98 ; 218.29,17.92 CONN4.P3-11 ; CONN4.P3-11 220.18,17.92 ; CONN4.P3-11 219.24,16.98 ; CONN4.P3-11 219.24,18.86 ; CONN2.P3-11 94.64,18.86 ; CONN2.P3-11 93.69,17.92 ; CONN2.P3-11 94.64,16.98 ; CONN2.P3-11 95.58,17.92 ; CONN4.P1-21 211.62,21.4 ; CONN4.P1-21 211.62,19.52 ; CONN4.P1-21 210.67,20.46 ; CONN4.P1-21 212.56,20.46 ; 208.13,17.92 CONN4.P3-22 ; CONN4.P3-22 209.08,16.98 ; CONN4.P3-22 209.08,18.86 ; CONN4.P3-22 210.02,17.92
  BOTTOM w0.381: v2(237.01,26.04) 237.01,25.93 236.47,25.4 R27.1 ; R21.1 v2(174.24,26.06) ; v2(50.29,25.91) 49.73,25.35 R9.1 ; v2(113.08,25.09) 112.83,25.35 R15.1 ; CONN1.P1-23 v1(19.63,26.85)
